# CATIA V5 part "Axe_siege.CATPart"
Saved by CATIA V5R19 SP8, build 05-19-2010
Part number: Axe_siege
Material "Acier": density 7860 kg/m3, Young's modulus 2e+11 Pa, Poisson ratio 0.266, thermal expansion 1.17e-05 1/K
Bounding box of the stored display mesh (mm): x -99.819 to 99.819, y 200 to 400, z 300 to 500
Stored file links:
  G:\EU_thinkMotion\CFAO_2010\MMS_groupe2\MMS_groupe2\OK\nrosalie\nrosalie_cfao_support_d_arme_legere_final\Axe_siege.CATPart
  G:\EU_thinkMotion\CFAO_2010\MMS_groupe2\MMS_groupe2\OK\nrosalie\nrosalie_cfao_support_d_arme_legere_final\Support_siege.CATPart
  G:\EU_thinkMotion\CFAO_2010\MMS_groupe2\MMS_groupe2\OK\nrosalie\nrosalie_cfao_support_d_arme_legere_final\nrosalie_Support_d_arme_legere.CATProduct
  G:\EU_thinkMotion\CFAO_2010\MMS_groupe2\MMS_groupe2\OK\nrosalie\nrosalie_cfao_support_d_arme_legere_final\Squelette_Colone.CATPart
  C:\Program Files\Dassault Systemes\B19\intel_a\startup\materials\French\Catalog.CATMaterial
  C:\Program Files\Dassault Systemes\B19\intel_a\startup\materials\darkbrown_leather.jpg
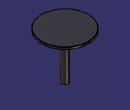
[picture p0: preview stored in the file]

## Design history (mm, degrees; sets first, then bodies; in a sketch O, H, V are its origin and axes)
Set1
  Line1 "Axe_siege": linked copy from another document
  Point1 "Centre_axe_siege": linked copy from another document
Body1 (main body), material "Acier"
  Sketch1 on yz-plane, origin (0, 0, 0), H (0, 1, 0), V (0, 0, 1)
    line L1 (200, 500) -> (300, 500)
    line L2 (300, 500) -> (300, 300)
    line L3 (285, 490) -> (200, 490)
    line L4 (200, 490) -> (200, 500)
    point P3 (300, 300)
    line L5 (285, 490) -> (285, 300)
    line L6 (285, 300) -> (300, 300)
    point P7 (300, 300)
    reference projected line E1 (300, 400) -> (300, 800) from Line1
    reference projected point E2 (300, 500) from Point1
    distance L5 L2 = 15
    length L1 = 100
    distance L1 L3 = 10
    distance L6 L1 = 200
    horizontal: L1 H, L3 H, L6 H
    vertical: L2 V, L4 V, L5 V
    coincidence: P3 P7, L2 E1, L1 E2
  Shaft1: profile Sketch1, axis Line1, angle 360
  Chamfer1: length 1, angle 45, on edge [face of Shaft1 from Sketch1.L6 | face of Shaft1 from Sketch1.L5]; edge [face of Shaft1 from Sketch1.L3 | face of Shaft1 from Sketch1.L4]; edge [face of Shaft1 from Sketch1.L4 | face of Shaft1 from Sketch1.L1]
